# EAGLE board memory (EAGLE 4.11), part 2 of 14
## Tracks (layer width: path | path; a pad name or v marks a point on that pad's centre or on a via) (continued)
-(WTX*ROTR)  (via drill 0.61) (continued)
  Bottom 0.254: v173.35,353.7 174.62,354.97 179.07,354.97 A26.V2 | v293.37,412.12 292.74,412.75 268.61,412.75 267.97,413.39 251.46,413.39 250.19,414.66 196.85,414.66 195.58,413.39 v190.5,413.39
-(WTX*TAD)  (via drill 0.61)
  Top 0.254: v384.18,276.23 384.18,262.25 385.44,260.99 C10.E2 | v341,281.31 341,287.02 339.73,288.29 v339.73,339.73 | 319.4,353.06 319.4,354.97 A15.V2 | v319.4,341.63 319.4,353.06 | v311.79,385.45 314.32,382.91 314.32,358.14 319.4,353.06
  Route3 0.254: v286.38,391.16 284.48,393.06 284.48,396.24 A18.E2
  Bottom 0.254: v384.18,276.23 381.63,278.77 371.48,278.77 370.84,278.13 367.67,278.13 367.03,278.77 354.33,278.77 351.79,281.31 v341,281.31 | v339.73,339.73 337.82,341.63 v319.4,341.63 | v311.79,385.45 307.98,385.45 306.7,386.72 A16.J2 306.07,387.99 303.53,387.99 302.26,389.25 294.64,389.25 291.46,392.43 290.19,392.43 289.56,391.8 287.02,391.8 v286.38,391.16
-[(ISZ*ZI)+JMS+(OP+IOT)*SKP+JMP]  (via drill 0.61)
  Top 0.254: v224.79,327.03 225.43,327.66 225.43,339.09 224.16,340.36 224.16,344.81 227.97,348.62 227.97,351.79 226.06,353.7 226.06,354.33 v227.33,355.6
  Route2 0.254: v179.07,80.64 179.71,80.01 184.78,80.01 191.77,73.02 220.98,73.02 223.52,70.48 238.12,70.48 255.91,52.7 262.25,52.7 263.52,51.44 267.97,51.44 F19.F2 | v179.71,248.28 183.51,252.09 184.78,252.09 188.59,255.91 189.87,255.91 193.04,252.73 198.12,252.73 v199.39,254 | v227.33,355.6 229.87,353.06 v233.04,353.06 | v306.7,364.49 308.61,366.4 314.96,366.4 315.6,367.03 324.49,367.03 325.12,366.4 327.66,366.4 328.3,367.03 334.64,367.03 337.82,370.21 340.36,370.21 341,369.57 349.88,369.57 353.69,373.38 362.58,373.38 366.39,369.57 375.29,369.57 379.1,373.38 379.73,373.38 381,372.11 385.44,372.11 A10.P2
  Route3 0.254: v179.07,80.64 171.45,88.27 171.45,148.59 161.93,158.11 161.93,182.88 v160.66,184.15 | v169.54,187.96 171.45,189.86 171.45,215.26 174.62,218.44 174.62,241.94 179.71,247.01 v179.71,248.28 | v199.39,254 209.55,264.16 209.55,275.59 219.07,285.12 219.07,292.74 219.71,293.37 219.71,294 219.07,294.64 219.07,321.31 v224.79,327.03 | v300.99,358.78 v306.7,364.49
  Bottom 0.254: v160.66,184.15 162.56,186.06 167.64,186.06 v169.54,187.96 | v233.04,353.06 251.46,353.06 252.73,354.33 260.99,354.33 261.62,353.7 270.51,353.7 274.32,357.5 275.59,357.5 277.5,355.6 278.76,355.6 280.67,357.5 287.65,357.5 288.29,358.14 289.56,356.87 297.18,356.87 299.72,359.41 300.36,359.41 v300.99,358.78
-[A12*(EX+DC+LD)]  (via drill 0.61)
  Top 0.254: v74.3,230.5 79.38,235.59 79.38,275.59 80.64,276.86 v80.64,287.02 | v355.6,389.25 355.6,382.91 356.87,381.64 A12.L2
  Route2 0.254: v267.33,378.46 267.33,377.19 266.7,377.19 259.08,369.57 250.19,369.57 249.56,370.21 240.66,370.21 236.85,366.4 234.31,366.4 231.14,369.57 224.79,369.57 220.98,373.38 212.09,373.38 211.46,372.75 202.56,372.75 201.93,373.38 199.39,373.38 195.58,369.57 189.23,369.57 186.06,366.4 177.16,366.4 176.53,367.03 173.99,367.03 173.35,366.4 164.47,366.4 163.83,367.03 161.29,367.03 157.48,363.22 148.59,363.22 144.78,367.03 135.89,367.03 135.25,366.4 129.54,366.4 v125.09,361.95
  Route3 0.254: v80.64,287.02 79.38,288.29 79.38,296.55 78.11,297.81 B34.R2 | v313.06,390.53 301.62,379.1 301.62,373.38 298.45,370.21 295.91,370.21 286.38,379.73 275.59,379.73 275.59,377.83 274.32,376.56 267.97,376.56 267.97,377.83 v267.33,378.46 | v125.09,361.95 95.25,332.11 95.25,306.71 v93.34,304.8
  Bottom 0.254: v74.3,230.5 73.66,229.87 67.31,229.87 60.96,223.52 52.07,223.52 48.26,227.33 39.37,227.33 35.56,223.52 31.11,223.52 30.48,222.88 C38.U2 | v355.6,389.25 354.96,388.62 351.79,388.62 351.15,389.25 342.26,389.25 341.63,388.62 340.36,388.62 339.09,389.89 336.55,389.89 335.92,389.25 332.11,389.25 328.93,392.43 326.39,392.43 322.58,388.62 314.96,388.62 v313.06,390.53 | v93.34,304.8 92.08,303.53 85.09,303.53 80.64,299.09 78.11,299.09 B34.R2
-[WTD+WTE+WTF+EX+DC+(WTX*JMS)+WTB]
  Top 0.254: D09.L2 394.97,175.26 394.97,179.07 393.7,180.34 393.7,200.66 395.61,202.56 395.61,217.17 396.88,218.44 396.88,239.39 395.61,240.66 395.61,243.84 C09.L2
-[WTE*[(ISZ*ZI)+JMS+(OP+IOT)*SKP]]  (via drill 0.61)
  Top 0.254: v365.12,260.35 365.12,238.76 369.57,238.76 C11.N2 | v359.41,261.62 358.77,262.25 v358.77,346.08 | v330.2,346.08 v330.2,361.31 | v339.73,368.94 339.73,398.78 343.54,398.78 346.71,395.61 346.71,391.8 347.35,391.16 A13.H2
  Bottom 0.254: A18.S2 284.48,364.49 288.93,364.49 290.19,363.22 291.46,363.22 292.1,363.86 302.26,363.86 302.89,363.22 311.79,363.22 315.6,367.03 318.77,367.03 320.04,365.76 321.94,365.76 A15.S2 322.58,364.49 327.02,364.49 328.3,363.22 | v365.12,260.35 363.86,261.62 v359.41,261.62 | v358.77,346.08 358.14,346.71 330.83,346.71 v330.2,346.08 | v330.2,361.31 328.3,363.22 | v339.73,368.94 339.73,366.4 332.11,366.4 328.93,363.22 328.3,363.22
-[WTF*-(OP+IOT)]  (via drill 0.61)
  Top 0.254: v410.85,303.53 410.85,307.34 B08.M2
  Route2 0.254: v300.36,295.28 302.26,297.18 309.25,297.18 309.88,296.55 314.96,296.55 315.6,297.18 321.94,297.18 322.58,296.55 327.66,296.55 331.47,300.36 340.36,300.36 341,299.72 v341.63,299.72 | v360.68,299.72 361.31,300.36 365.76,300.36 366.39,299.72 375.29,299.72 379.1,303.53 387.99,303.53 391.8,299.72 400.69,299.72 404.5,303.53 v410.85,303.53
  Bottom 0.254: v300.36,295.28 297.18,295.28 B17.S2 | v341.63,299.72 342.26,300.36 353.06,300.36 353.69,299.72 v360.68,299.72
-[WTF+WTX*(JMP+JMS)+WTE+WTB+EX+DC+LD]  (via drill 0.61)
  Route2 0.254: v409.57,338.46 408.94,337.82 402.59,337.82 398.14,342.27 374.65,342.27 373.38,343.54 340.36,343.54 338.45,341.63 320.68,341.63 319.4,342.9 314.96,342.9 314.32,342.27 305.44,342.27 304.8,341.63 299.72,341.63 299.08,341 294,341 290.83,337.82 288.29,337.82 287.65,338.46 v287.02,338.46
  Route3 0.254: v409.57,338.46 409.57,320.04 412.12,317.5 412.12,316.23 410.85,316.23 410.21,316.87 408.31,316.87 B08.J2 | v287.02,338.46 285.75,337.19 285.75,328.93 284.48,327.66 B18.E2
-[WTX(TAD+IAC_CMA)]  (via drill 0.61)
  Top 0.254: v217.81,247.65 219.07,246.38 219.07,217.81 222.25,214.63 v222.25,144.14 | v309.25,143.51 309.88,142.88 v309.88,140.97
  Route2 0.254: v182.88,250.19 184.15,248.92 187.96,248.92 188.59,249.56 197.49,249.56 198.12,248.92 200.66,248.92 204.47,252.73 211.46,252.73 216.53,247.65 v217.81,247.65 | v309.88,140.97 319.4,140.97 322.58,137.79 327.66,137.79 328.3,138.43 330.83,138.43 334.01,135.25 338.45,135.25 347.98,125.73 349.88,125.73 350.52,125.09 353.06,125.09 353.69,125.73 354.96,125.73 357.5,123.19 366.39,132.08 374.01,132.08 v382.9,123.19
  Route3 0.254: v182.88,250.19 165.1,267.97 165.1,292.74 168.28,295.91 168.28,315.6 167,316.87 B27.J2 | v382.9,123.19 387.35,118.74 387.35,78.74 384.18,75.56 381.63,75.56 381.63,81.28 382.27,81.91 E10.V2
  Bottom 0.254: v222.25,144.14 261.62,144.14 263.52,142.24 303.53,142.24 304.8,143.51 v309.25,143.51
-[WTX*(JMP+JMS)]  (via drill 0.61)
  Top 0.254: v393.7,356.24 393.7,362.59 396.88,365.76 396.88,372.75 395.61,374.02 A09.N2 | v363.86,353.7 364.49,353.06 364.49,339.73 361.95,337.19 v361.95,330.84
  Bottom 0.254: B34.E2 81.28,327.66 81.92,328.3 86.36,328.3 87,328.93 95.89,328.93 96.52,328.3 99.06,328.3 99.69,328.93 107.31,328.93 107.95,328.3 111.76,328.3 112.39,328.93 121.28,328.93 121.92,328.3 124.46,328.3 125.09,328.93 133.99,328.93 134.62,328.3 137.16,328.3 137.79,328.93 146.69,328.93 147.32,328.3 149.86,328.3 150.5,328.93 159.38,328.93 160.02,328.3 162.56,328.3 163.19,328.93 172.09,328.93 172.72,328.3 175.26,328.3 175.9,328.93 184.78,328.93 185.42,328.3 187.96,328.3 188.59,328.93 197.49,328.93 198.12,328.3 200.66,328.3 201.29,328.93 210.19,328.93 210.82,328.3 213.36,328.3 214,328.93 222.88,328.93 223.52,328.3 226.06,328.3 226.69,328.93 235.59,328.93 236.22,328.3 238.76,328.3 239.4,328.93 248.28,328.93 248.92,328.3 251.46,328.3 252.09,328.93 260.99,328.93 261.62,328.3 264.16,328.3 264.8,328.93 273.69,328.93 274.32,328.3 276.86,328.3 277.5,328.93 278.76,328.93 279.4,328.3 289.56,328.3 290.19,328.93 299.08,328.93 299.72,328.3 302.26,328.3 302.89,328.93 311.79,328.93 312.42,328.3 314.96,328.3 315.6,328.93 316.87,328.93 317.5,328.3 327.66,328.3 328.3,328.93 337.19,328.93 337.82,328.3 340.36,328.3 341,328.93 346.07,328.93 347.35,327.66 B13.E2 347.98,327.66 350.52,327.66 354.33,331.47 358.14,331.47 358.77,330.84 v361.95,330.84 | v393.7,356.24 393.7,353.7 v363.86,353.7
-A  (via drill 0.61)
  Top 0.254: A32.N2 103.5,375.29 104.78,376.56 104.78,379.1 106.05,380.37 106.05,383.54 A32.K2 | 117.47,376.56 116.2,375.29 A31.N2 | 117.47,376.56 117.47,382.27 118.75,383.54 A31.K2 | A29.K2 144.78,384.81 146.05,386.08 146.05,393.06 141.6,397.51 141.6,399.42 A29.D2 | 130.18,382.27 130.18,376.56 128.91,375.29 A30.N2 | 130.18,382.27 131.44,383.54 A30.K2 | 130.18,382.27 130.18,398.15 128.91,399.42 A30.D2 | 117.47,376.56 117.47,360.68 118.75,359.41 A31.U2 | 117.47,325.75 117.47,328.3 116.2,329.56 B31.D2 | 117.47,325.75 117.47,294 116.2,292.74 B31.T2 | 130.18,328.3 130.18,325.12 | 130.18,325.12 130.18,316.87 | 130.18,316.87 130.18,300.36 128.91,299.09 B30.R2 | 130.18,328.3 128.91,329.56 B30.D2 | 139.7,329.56 136.53,329.56 136.53,323.22 134.62,321.31 | 139.7,329.56 140.97,329.56 B29.D2 | 130.18,316.87 134.62,321.31 | 134.62,321.31 v141.6,314.33 | v266.7,341.63 266.7,332.11 267.97,330.84 B19.D2 | v140.34,341.63 139.7,341 139.7,329.56 | 117.47,325.75 124.46,325.75 125.09,325.12 130.18,325.12 | 130.18,328.3 130.18,356.87 131.44,358.14 A30.U2
  Route2 0.254: v141.6,314.33 144.15,314.33 B29.K2
  Bottom 0.254: A32.U2 106.68,359.41 107.31,360.05 111.76,360.05 112.39,360.68 117.47,360.68 118.75,359.41 A31.U2 119.38,359.41 121.92,359.41 123.19,360.68 130.18,360.68 131.44,359.41 A30.U2 | A32.K2 106.68,384.81 111.12,384.81 112.39,386.08 113.67,386.08 114.94,384.81 118.75,384.81 A31.K2 | A32.D2 103.5,400.69 104.78,401.96 111.76,401.96 113.03,400.69 115.57,400.69 A31.D2 116.2,400.69 117.47,401.96 124.46,401.96 125.73,400.69 128.27,400.69 A30.D2 | A29.K2 144.15,384.81 139.7,384.81 138.43,386.08 137.79,386.08 136.53,384.81 132.08,384.81 A30.K2 | A31.N2 116.2,374.02 117.47,372.75 124.46,372.75 125.73,374.02 128.27,374.02 A30.N2 | v140.34,341.63 v266.7,341.63
-A00  (via drill 0.61)
  Top 0.254: v114.3,205.74 114.3,163.83 115.57,162.56 D31.R2 | v357.5,111.76 355.6,113.66 v355.6,139.7 | v121.28,141.6 120.65,142.24 v120.65,161.29 | 44.45,278.13 44.45,249.56 43.18,248.28 C37.K2 | 44.45,278.13 44.45,328.3 | 44.45,328.3 44.45,369.57 43.18,370.84 A37.P2 | 44.45,328.3 v45.09,328.3 | v146.05,279.4 146.05,306.07 144.78,307.34 B29.M2 144.78,308.61 144.78,312.42 149.22,316.87 149.22,345.44 v153.03,349.25 | 44.45,278.13 v46.35,278.13 | v252.73,400.05 250.82,398.15 v250.82,348.62
  Route2 0.254: v357.5,111.76 360.05,111.76 E12.K2 | v252.73,400.05 255.27,400.05 A20.D2
  Route3 0.254: 31.75,206.38 v31.75,247.01 31.75,252.09 30.48,253.36 C38.H2 | 31.75,206.38 31.75,179.7 30.48,178.44 D38.K2 | v30.48,206.38 31.75,206.38
  Bottom 0.254: v114.3,205.74 46.35,205.74 45.72,206.38 v30.48,206.38 | v355.6,139.7 354.96,140.34 321.31,140.34 320.68,139.7 313.69,139.7 312.42,138.43 306.07,138.43 305.44,139.06 297.81,139.06 297.18,138.43 293.37,138.43 292.1,139.7 142.88,139.7 140.97,141.6 v121.28,141.6 | v120.65,161.29 116.2,161.29 D31.R2 | v31.75,247.01 33.02,247.01 34.29,245.75 36.83,245.75 38.1,247.01 42.55,247.01 C37.K2 | v45.09,328.3 46.35,328.3 46.99,328.93 49.53,328.93 50.16,328.3 59.05,328.3 59.69,328.93 62.23,328.93 62.87,328.3 71.75,328.3 72.39,328.93 76.83,328.93 77.47,329.56 B34.D2 | v146.05,279.4 145.41,280.04 59.69,280.04 59.05,279.4 48.9,279.4 47.62,278.13 v46.35,278.13 | v250.82,348.62 235.59,348.62 234.31,349.89 225.43,349.89 224.79,349.25 210.82,349.25 210.19,349.89 181.61,349.89 180.97,350.52 167.64,350.52 167,349.89 153.67,349.89 v153.03,349.25
-A1  (via drill 0.61)
  Top 0.254: v408.31,271.78 407.04,273.05 407.04,281.31 v407.67,281.94
  Route2 0.254: v408.31,97.79 422.91,112.39 427.36,112.39 434.98,120.02 434.98,142.88 436.25,144.14 436.25,151.13 435.61,151.13 434.98,151.76 434.98,163.83 v433.7,163.83 | v442.6,217.81 442.6,219.07 447.68,224.16 447.68,233.04 442.6,233.04 409.57,266.06 409.57,271.78 v408.31,271.78 | v407.67,281.94 396.24,293.37 389.89,293.37 388.62,294.64 386.08,294.64 B10.S2
  Route3 0.254: v442.6,180.97 441.96,181.61 441.96,182.88 441.32,183.51 441.32,184.78 442.6,186.06 442.6,188.59 441.32,189.86 441.32,206.38 442.6,207.64 v442.6,217.81
  Bottom 0.254: v408.31,97.79 401.32,90.8 396.88,90.8 395.61,89.53 E09.T2 | v433.7,163.83 433.7,167 432.44,167 431.8,167.64 431.8,175.89 436.88,175.89 441.96,180.97 v442.6,180.97
-A12  (via drill 0.61)
  Top 0.254: C38.S2 29.84,229.23 29.84,234.31 C38.P2 29.84,235.59 28.57,236.85 v28.57,283.85 | B35.D2 64.77,329.56 63.5,328.3 63.5,308.61 64.77,307.34 64.77,305.44 B35.N2 64.77,304.17 63.5,302.9 63.5,285.75 v61.59,283.85 | B27.S2 169.54,295.91 169.54,300.99 B27.P2 170.18,302.26 170.18,306.07 171.45,307.34 171.45,318.77 170.18,320.04 B27.H2 | v266.7,393.7 266.7,398.15 267.97,399.42 A19.D2 267.97,400.69 266.7,401.96 v266.7,420.37 | v309.88,394.97 309.88,391.16 A16.H2 | B30.T2 128.91,291.47 128.91,289.56 138.43,280.04 138.43,276.23 139.7,274.96 140.97,274.96 140.97,285.12 B29.V2 141.6,286.39 142.88,287.66 142.88,306.71 | A28.S2 157.48,365.76 158.75,367.03 158.75,388.62 157.48,389.89 A28.H2 156.84,391.16 156.84,396.24 A28.E2 157.48,397.51 158.75,398.78 v158.75,419.1 | A29.N2 141.6,374.02 141.6,371.48 v147.96,365.12 142.88,360.05 142.88,306.71 | 142.88,306.71 v143.51,306.71 | v122.56,295.28 120.65,297.18 120.65,312.42 119.38,313.69 B31.K2 | F37.P2 42.55,27.94 42.55,22.86 F37.S2 43.18,21.59 47.62,21.59 v47.62,4.44 | v473.07,5.71 473.07,13.97 474.35,15.24 F03.U2 | v395.61,1.9 393.7,3.81 393.7,156.84 394.97,158.11 394.97,161.29 D09.R2 395.61,162.56 395.61,163.19 396.88,164.47 396.88,191.77 395.61,193.04 D09.D2 | F23.K2 220.98,40.64 221.62,40.01 221.62,36.2 222.25,35.56 222.25,4.44 v222.88,3.81 222.88,2.54 v222.25,1.9 | v33.66,179.07 33.66,176.53 34.92,175.26 v34.92,162.56
  Route3 0.254: v33.66,227.33 34.92,226.06 34.92,180.34 v33.66,179.07 | v34.92,162.56 34.92,51.44 44.45,41.91 44.45,30.48 43.18,29.21 F37.P2
  Bottom 0.254: B35.N2 65.41,304.17 66.67,302.9 73.66,302.9 74.93,304.17 77.47,304.17 B34.N2 78.11,304.8 80.64,304.8 85.72,309.88 87.63,309.88 88.27,309.25 97.16,309.25 100.97,313.06 109.86,313.06 110.49,312.42 113.03,312.42 114.3,313.69 118.75,313.69 B31.K2 | v28.57,283.85 29.21,283.21 52.07,283.21 52.7,283.85 v61.59,283.85 | B22.J2 229.87,317.5 226.06,317.5 224.16,319.41 215.26,319.41 214.63,318.77 212.09,318.77 211.46,319.41 202.56,319.41 201.93,318.77 199.39,318.77 198.75,319.41 191.77,319.41 191.13,318.77 186.69,318.77 186.06,319.41 177.16,319.41 176.53,318.77 175.26,318.77 173.99,320.04 170.18,320.04 B27.H2 | v266.7,393.7 266.7,395.61 274.32,395.61 277.5,398.78 286.38,398.78 287.02,398.15 289.56,398.15 290.19,398.78 297.18,398.78 300.99,394.97 v309.88,394.97 | v147.96,365.12 149.86,363.22 155.57,363.22 156.84,364.49 A28.S2 | v266.7,420.37 266.06,421 173.99,421 172.09,419.1 v158.75,419.1 | v143.51,306.71 147.96,306.71 148.59,306.07 151.13,306.07 151.76,306.71 160.66,306.71 163.83,303.53 168.28,303.53 169.54,302.26 B27.P2 | v122.56,295.28 125.09,292.74 128.27,292.74 B30.T2 | D10.D2 382.9,194.31 384.18,195.58 389.89,195.58 391.8,193.67 394.97,193.67 D09.D2 | v473.07,5.71 469.26,1.9 v395.61,1.9 394.97,2.54 377.82,2.54 376.56,1.27 288.93,1.27 287.02,3.17 285.12,3.17 283.85,1.9 224.79,1.9 v222.88,3.81 | v47.62,4.44 51.44,0.63 198.12,0.63 200.03,2.54 200.66,1.9 v222.25,1.9 | v33.66,227.33 31.11,227.33 30.48,227.97 C38.S2
-A13  (via drill 0.61)
  Top 0.254: v222.25,58.42 v222.25,70.48 222.25,102.87 223.52,104.14 v223.52,104.77 | v349.25,71.75 v349.25,80.64 349.25,109.22 352.43,112.39 v352.43,127 | D31.J2 116.2,181.61 116.84,182.25 116.84,186.06 117.47,186.69 117.47,218.44 123.83,224.79 123.83,316.87 128.27,321.31 128.27,323.22 B30.F2 | v155.57,323.85 155.57,328.3 154.31,329.56 B28.D2 | B10.N2 382.9,305.44 382.9,309.25 385.44,311.79 385.44,313.69 B10.K2 | B12.U2 360.68,289.56 361.95,290.83 361.95,312.42 360.68,313.69 B12.K2 360.68,314.96 361.95,316.23 v361.95,329.56 | v274.32,363.86 276.23,363.86 276.23,332.74 v279.4,329.56
  Route2 0.254: B12.D2 356.87,329.56 353.06,329.56 351.79,328.3 350.52,328.3 349.88,328.93 341,328.93 340.36,328.3 337.82,328.3 337.19,328.93 328.3,328.93 327.66,328.3 317.5,328.3 316.87,328.93 315.6,328.93 314.96,328.3 312.42,328.3 311.79,328.93 302.89,328.93 302.26,328.3 299.72,328.3 299.08,328.93 290.19,328.93 289.56,328.3 280.67,328.3 v279.4,329.56 278.13,329.56 276.86,328.3 274.32,328.3 273.69,328.93 264.8,328.93 264.16,328.3 257.81,328.3 254.63,325.12 252.09,325.12 248.28,328.93 239.4,328.93 238.76,328.3 236.22,328.3 235.59,328.93 226.69,328.93 226.06,328.3 223.52,328.3 222.88,328.93 214,328.93 213.36,328.3 210.82,328.3 210.19,328.93 201.29,328.93 200.66,328.3 198.12,328.3 197.49,328.93 188.59,328.93 187.96,328.3 185.42,328.3 184.78,328.93 175.9,328.93 175.26,328.3 172.72,328.3 172.09,328.93 163.19,328.93 160.02,325.75 157.48,325.75 v155.57,323.85 | v223.52,104.77 219.07,109.22 214,109.22 207.65,115.57 205.74,115.57 174.62,146.69 171.45,146.69 167.64,150.5 v163.19,150.5
  Route3 0.254: v297.18,70.48 v297.18,73.02 | v268.61,365.12 268.61,367.67 A19.R2 | v128.91,157.48 120.65,165.73 120.65,173.99 116.2,178.44 116.2,180.34 D31.J2
  Bottom 0.254: v222.25,58.42 218.44,58.42 217.81,57.79 F23.D2 | v222.25,70.48 236.22,70.48 236.85,71.12 296.55,71.12 v297.18,70.48 | v297.18,73.02 297.81,72.39 300.99,72.39 301.62,71.75 303.53,71.75 304.17,71.12 348.62,71.12 v349.25,71.75 | v352.43,127 356.87,127 E12.D2 | v349.25,80.64 401.95,80.64 402.59,81.28 408.31,81.28 408.94,80.64 446.4,80.64 455.93,90.17 462.28,90.17 467.36,95.25 471.17,95.25 E03.R2 | v155.57,323.85 155.57,323.22 154.94,322.58 148.59,322.58 147.96,321.95 139.06,321.95 138.43,322.58 135.89,322.58 135.25,321.95 130.18,321.95 128.91,323.22 B30.F2 | B12.U2 360.68,289.56 361.31,290.2 365.76,290.2 366.39,290.83 368.3,290.83 370.2,288.93 372.75,288.93 B11.U2 373.38,288.29 375.92,288.29 377.19,287.02 384.18,287.02 385.44,288.29 B10.U2 386.08,289.56 388.62,289.56 389.89,290.83 396.88,290.83 398.14,289.56 B09.U2 | B12.K2 360.68,314.96 365.12,314.96 366.39,316.23 367.67,316.23 368.94,314.96 372.75,314.96 B11.K2 373.38,314.96 377.82,314.96 379.1,316.23 380.37,316.23 381.63,314.96 385.44,314.96 B10.K2 | B12.N2 357.5,304.17 358.77,302.9 365.76,302.9 367.03,304.17 369.57,304.17 B11.N2 370.2,304.17 371.48,302.9 378.46,302.9 379.73,304.17 382.27,304.17 B10.N2 382.9,304.17 384.18,302.9 389.25,302.9 391.16,304.8 394.97,304.8 B09.N2 | 361.95,328.3 365.76,328.3 367.03,329.56 369.57,329.56 B11.D2 370.2,329.56 371.48,328.3 376.56,328.3 377.19,328.93 381.63,328.93 382.27,329.56 B10.D2 | 361.95,328.3 358.77,328.3 357.5,329.56 B12.D2 | v268.61,365.12 269.88,363.86 v274.32,363.86 | 361.95,328.3 v361.95,329.56 | v163.19,150.5 162.56,151.13 154.31,151.13 153.67,150.5 152.4,151.76 152.4,154.31 148.59,154.31 147.96,153.67 139.06,153.67 135.25,157.48 v128.91,157.48
-A13(B)  (via drill 0.61)
  Top 0.254: v99.69,87.63 98.42,88.9 98.42,137.79 100.97,140.34 100.97,151.13 101.6,151.76 101.6,170.81 104.78,173.99 104.78,178.44 v106.68,180.34
  Route2 0.254: v106.68,180.34 113.03,186.69 115.57,186.69 D31.F2
  Bottom 0.254: v99.69,87.63 102.87,87.63 102.87,83.18 E32.V2
-A(00-01)  (via drill 0.61)
  Route2 0.254: v291.46,393.7 286.38,398.78 276.86,398.78 273.05,394.97 262.89,394.97 262.25,395.61 253.37,395.61 249.56,391.8 240.66,391.8 236.85,395.61 227.97,395.61 224.16,391.8 219.71,391.8 v215.26,387.35
  Route3 0.254: v141.6,326.39 141.6,324.49 B29.F2 | v215.26,387.35 196.85,368.94 196.85,363.86 193.68,360.68 193.68,341.63 184.15,332.11 184.15,328.93 185.42,327.66 v182.25,324.49
  Bottom 0.254: v141.6,326.39 142.24,325.75 146.05,325.75 146.69,326.39 149.22,326.39 150.5,325.12 159.38,325.12 160.02,325.75 162.56,325.75 163.19,325.12 168.28,325.12 169.54,326.39 B27.E2 170.18,326.39 173.99,326.39 175.26,325.12 176.53,325.12 177.16,324.49 177.8,324.49 177.8,323.22 178.44,322.58 180.34,322.58 v182.25,324.49 | v291.46,393.7 293.37,391.8 300.36,391.8 300.99,392.43 311.15,392.43 311.15,394.97 309.88,396.24 A16.E2
-A(00-11)  (via drill 0.61)
  Top 0.254: v133.35,302.26 133.35,312.42 132.08,313.69 B30.K2 | A16.P2 309.25,370.84 309.25,365.76 A16.S2 309.25,364.49 307.98,363.22 v307.98,350.52 | B18.K2 283.85,314.96 283.21,315.6 283.21,318.77 282.57,319.41 282.57,328.3 281.31,329.56 B18.D2 280.67,330.84 279.4,332.11 v279.4,353.7
  Route2 0.254: v366.39,231.78 358.77,239.39 353.69,239.39 349.25,243.84 v347.98,243.84 | v328.3,299.09 321.31,306.07 313.69,306.07 309.88,309.88 300.99,309.88 297.18,306.07 288.29,306.07 287.65,306.71 287.02,306.71 285.75,307.98 285.75,313.69 284.48,313.69 B18.K2
  Route3 0.254: v114.3,318.14 114.3,321.95 115.57,323.22 B31.F2 | v382.9,222.25 385.44,219.71 385.44,208.28 384.18,207.01 384.18,179.7 385.44,178.44 D10.K2 | v341,244.47 339.73,245.75 339.73,281.94 330.2,291.47 330.2,297.18 v328.3,299.09
  Bottom 0.254: v133.35,302.26 136.53,299.09 140.97,299.09 B29.R2 | v114.3,318.14 114.3,315.6 124.46,315.6 125.09,316.23 130.18,316.23 131.44,314.96 B30.K2 132.08,314.96 132.72,315.6 137.16,315.6 137.79,316.23 146.69,316.23 147.32,315.6 149.86,315.6 150.5,316.23 159.38,316.23 160.02,315.6 162.56,315.6 163.19,316.23 172.09,316.23 172.72,315.6 175.26,315.6 175.9,316.23 184.78,316.23 185.42,315.6 187.96,315.6 188.59,316.23 197.49,316.23 198.12,315.6 200.66,315.6 201.29,316.23 210.19,316.23 210.82,315.6 213.36,315.6 214,316.23 222.88,316.23 223.52,315.6 226.06,315.6 226.69,316.23 228.6,316.23 230.5,314.33 233.04,314.33 B22.K2 233.68,314.96 234.31,315.6 238.76,315.6 239.4,316.23 248.28,316.23 248.92,315.6 251.46,315.6 252.09,316.23 260.99,316.23 261.62,315.6 264.16,315.6 264.8,316.23 273.69,316.23 274.32,315.6 276.86,315.6 277.5,316.23 282.57,316.23 283.85,314.96 B18.K2 | D10.K2 386.08,178.44 390.52,178.44 391.8,179.7 392.43,179.7 393.7,178.44 398.14,178.44 D09.K2 | v307.98,350.52 307.34,349.89 294.64,349.89 291.46,353.06 280.04,353.06 v279.4,353.7 | v382.9,222.25 377.82,227.33 370.84,227.33 v366.39,231.78 | v347.98,243.84 347.35,243.2 342.9,243.2 341.63,244.47 v341,244.47
-A(00-12)
  Top 0.254: B28.N2 154.31,304.17 154.94,303.53 154.94,299.72 155.57,299.09 155.57,291.47 156.84,290.2 156.84,289.56 B28.U2
  Bottom 0.254: B29.T2 141.6,291.47 142.88,290.2 149.86,290.2 150.5,290.83 153.67,290.83 155.57,288.93 156.84,288.93 B28.U2
-AC11  (via drill 0.61)
  Top 0.254: v468,363.22 469.9,363.22 469.9,375.92 476.25,382.27 476.25,394.97 474.98,396.24 A03.E2 | v190.5,355.6 190.5,366.4 191.77,367.67 A25.R2 | v393.06,350.52 396.88,350.52 398.14,351.79 397.51,352.43 397.51,357.5 396.88,358.14 396.88,363.22 398.14,364.49 A09.S2 | v459.11,358.14 459.11,361.31 A04.T2
  Route2 0.254: v468,363.22 467.36,363.86 460.38,363.86 459.11,362.59 A04.T2
  Bottom 0.254: v190.5,355.6 190.5,353.06 210.82,353.06 212.09,351.79 247.65,351.79 248.92,350.52 249.56,351.16 270.51,351.16 271.78,349.89 288.29,349.89 290.19,351.79 293.37,348.62 324.49,348.62 325.12,349.25 357.5,349.25 358.77,350.52 v393.06,350.52 396.88,350.52 398.14,351.79 397.51,352.43 398.78,353.7 440.06,353.7 443.87,357.5 452.75,357.5 453.39,356.87 457.83,356.87 v459.11,358.14
-AM  (via drill 0.61)
  Top 0.254: v215.26,115.57 215.9,114.93 215.9,84.45 217.17,83.18 E23.V2 | v63.5,97.79 63.5,165.73 v62.23,167
  Bottom 0.254: v215.26,115.57 216.53,116.84 220.34,116.84 E23.H2 | 61.59,96.52 60.96,97.16 56.52,97.16 55.88,97.79 E36.P2 | 61.59,96.52 62.23,96.52 v63.5,97.79 | v62.23,167 55.24,173.99 52.7,173.99 D36.L2 | 61.59,96.52 74.3,83.82 74.93,83.82 75.56,84.45 85.72,84.45 85.72,82.55 87.63,80.64 88.9,80.64 88.9,83.18 89.53,83.82 93.98,83.82 100.33,90.17 106.68,90.17 110.49,93.98 120.65,93.98 124.46,90.17 132.08,90.17 135.89,93.98 144.78,93.98 148.59,90.17 157.48,90.17 161.29,93.98 163.83,93.98 164.47,93.34 173.35,93.34 173.99,93.98 182.88,93.98 189.87,86.99 198.75,86.99 199.39,87.63 207.65,87.63 210.82,90.8 212.72,90.8 215.9,87.63 222.25,87.63 222.25,85.09 221.62,84.45 219.07,84.45 217.81,83.18 E23.V2
-AND  (via drill 0.61)
  Top 0.254: 260.35,182.88 260.35,218.44 259.08,219.71 260.35,220.98 v260.35,294 260.35,309.25 259.08,310.52 259.08,313.69 B20.K2 | 260.35,182.88 260.35,151.76 259.08,150.5 259.08,149.86 260.35,148.59 260.35,85.09 259.08,83.82 259.08,69.85 v259.71,69.22 260.35,68.58 260.35,55.88 259.08,54.61 F20.E2 | v314.32,65.41 v314.32,26.03 | 260.35,182.88 v262.25,182.88
  Route2 0.254: v293.37,67.94 v293.37,65.41 | v266.06,180.97 267.97,182.88 276.23,182.88 292.1,167 296.55,167 296.55,170.81 D17.M2
  Route3 0.254: v347.35,311.15 347.35,313.69 B13.K2 | v332.11,309.25 333.38,307.98 v333.38,304.8
  Bottom 0.254: v314.32,26.03 318.77,26.03 F15.R2 | v314.32,65.41 304.17,65.41 303.53,64.77 300.99,64.77 300.36,65.41 v293.37,65.41 | v293.37,67.94 291.46,69.85 260.35,69.85 v259.71,69.22 | v266.06,180.97 265.43,181.61 263.52,181.61 v262.25,182.88 | v347.35,311.15 346.07,309.88 339.09,309.88 338.45,309.25 v332.11,309.25 | v333.38,304.8 333.38,303.53 327.02,303.53 320.68,297.18 313.69,297.18 313.06,296.55 304.17,296.55 303.53,297.18 300.99,297.18 300.36,296.55 291.46,296.55 290.83,297.18 288.29,297.18 287.65,296.55 278.76,296.55 278.13,297.18 275.59,297.18 271.78,293.37 262.89,293.37 262.25,294 v260.35,294
-AST  (via drill 0.61)
  Route2 0.254: v357.5,176.53 358.77,176.53 378.46,156.84 381.63,156.84 382.27,156.21 D10.T2 | v338.45,236.22 337.82,236.22 334.64,239.39 326.39,239.39 322.58,243.2 313.69,243.2 313.06,242.57 304.17,242.57 297.18,249.56 295.91,249.56 295.27,250.19 294.64,249.56 288.29,249.56 v287.65,248.92
  Route3 0.254: v357.5,176.53 353.06,180.97 353.06,182.88 352.43,183.51 352.43,189.23 351.15,190.5 351.15,191.77 352.43,193.04 352.43,206.38 353.69,207.64 353.69,220.34 352.43,221.61 352.43,231.14 353.69,232.41 v353.69,233.04 | v274.95,252.73 273.69,254 273.69,255.91 273.05,256.54 273.05,274.96 269.88,278.13 269.88,307.34 263.52,313.69 263.52,339.09 256.54,346.08 256.54,354.33 255.91,354.97 A20.V2
  Bottom 0.254: v353.69,233.04 353.06,233.68 344.81,233.68 341.63,236.85 339.09,236.85 v338.45,236.22 | v287.65,248.92 280.04,248.92 277.5,251.46 276.23,251.46 v274.95,252.73
-BAC00  (via drill 0.61)
  Top 0.254: v194.94,11.43 197.49,11.43 208.28,0.63 284.48,0.63 v284.48,5.71
  Route2 0.254: v17.78,100.33 21.59,96.52 23.5,96.52 109.22,10.79 163.83,10.79 164.47,11.43 172.09,11.43 172.72,10.79 194.31,10.79 v194.94,11.43 | v284.48,5.71 288.93,1.27 374.65,1.27 379.1,5.71 405.13,5.71 v406.4,6.98 | v424.18,100.96 438.15,114.93 438.15,137.79 436.88,139.06 436.88,151.13 437.51,151.13 441.32,154.94 441.32,182.25 443.23,182.25 445.77,184.78 445.77,186.69 D05.F2
  Route3 0.254: v406.4,6.98 412.75,13.34 412.75,59.05 419.1,65.41 419.1,85.09 425.45,91.44 425.45,99.69 v424.18,100.96
  Bottom 0.254: v17.78,100.33 13.34,100.33 10.16,103.5 3.17,103.5 3.17,118.11 10.79,125.73 13.34,125.73 13.97,126.36 E39.D2
-BAC01  (via drill 0.61)
  Route2 0.254: v80.64,149.86 73.03,142.24 71.75,142.24 60.96,131.44 54.61,131.44 45.09,121.92 36.2,121.92 32.38,125.73 23.5,125.73 22.86,125.09 18.41,125.09 17.78,124.46 E39.E2 | v125.73,154.31 126.36,153.67 137.16,153.67 140.97,157.48 149.86,157.48 150.5,156.84 159.38,156.84 160.02,157.48 162.56,157.48 163.19,156.84 169.54,156.84 175.9,150.5 v176.53,150.5 | v182.88,149.86 193.04,139.7 234.31,139.7 242.57,131.44 251.46,131.44 259.71,139.7 294,139.7 295.27,138.43 305.44,138.43 312.42,131.44 314.96,131.44 315.6,132.08 322.58,132.08 332.11,122.55 340.36,122.55 344.17,118.74 350.52,118.74 353.69,115.57 362.58,115.57 366.39,119.38 367.67,119.38 370.84,116.2 375.92,116.2 379.1,119.38 384.81,119.38 v389.25,123.82 | v398.78,174.62 409.57,185.42 416.56,185.42 422.91,191.77 429.26,191.77 429.89,192.41 435.61,192.41 v436.25,193.04
  Route3 0.254: v389.25,123.82 389.89,124.46 389.89,125.73 390.52,126.36 390.52,135.89 389.25,137.16 389.25,147.32 390.52,148.59 390.52,154.94 393.7,158.11 393.7,164.47 400.05,170.81 400.05,172.72 398.78,173.99 v398.78,174.62 | v436.25,193.04 438.15,191.13 438.15,189.23 436.88,187.96 v436.88,187.32
  Bottom 0.254: v80.64,149.86 83.19,147.32 99.06,147.32 102.87,151.13 111.76,151.13 112.39,150.5 121.28,150.5 125.09,154.31 v125.73,154.31 | v176.53,150.5 182.25,150.5 v182.88,149.86 | v436.88,187.32 441.96,182.25 445.13,182.25 445.77,181.61 D05.J2
-BAC02  (via drill 0.61)
  Route2 0.254: v49.53,115.57 52.7,118.74 59.69,118.74 80.01,139.06 97.16,139.06 105.41,147.32 143.51,147.32 147.32,151.13 149.86,151.13 v150.5,150.5 | v182.25,156.21 180.97,157.48 180.97,179.7 178.44,179.7 171.45,186.69 171.45,191.77 172.72,191.77 175.9,188.59 184.78,188.59 185.42,189.23 187.96,189.23 191.77,185.42 200.66,185.42 204.47,189.23 213.36,189.23 214,188.59 222.88,188.59 223.52,189.23 225.43,189.23 v229.87,184.78 | v252.73,180.97 257.18,185.42 264.16,185.42 270.51,191.77 275.59,191.77 v277.5,193.67 | v376.56,177.8 381.63,172.72 391.16,172.72 391.8,173.35 394.33,173.35 401.32,166.37 403.23,166.37 v405.13,168.28 | v427.36,170.18 427.99,169.54 430.53,169.54 434.98,173.99 v436.25,173.99
  Route3 0.254: v372.75,188.59 374.65,186.69 374.65,179.7 v376.56,177.8
  Bottom 0.254: v49.53,115.57 48.9,115.57 48.26,116.2 40.64,116.2 37.47,119.38 36.2,119.38 32.38,115.57 23.5,115.57 22.86,116.2 18.41,116.2 17.78,116.84 E39.H2 | v150.5,150.5 153.03,147.95 159.38,147.95 160.02,147.32 161.29,147.32 165.1,151.13 172.72,151.13 178.44,156.84 181.61,156.84 v182.25,156.21 | v229.87,184.78 230.5,185.42 234.95,185.42 235.59,184.78 238.12,184.78 239.4,186.06 246.38,186.06 251.46,180.97 v252.73,180.97 | v277.5,193.67 278.76,193.67 280.67,195.58 288.29,195.58 290.83,193.04 292.1,193.04 293.37,191.77 302.26,191.77 302.89,192.41 311.79,192.41 315.6,188.59 316.87,188.59 320.04,191.77 327.66,191.77 328.3,192.41 337.19,192.41 337.82,191.77 340.36,191.77 341,192.41 343.54,192.41 346.71,189.23 353.06,189.23 353.69,188.59 362.58,188.59 363.22,189.23 365.76,189.23 366.39,188.59 v372.75,188.59 | v405.13,168.28 407.04,170.18 413.38,170.18 414.65,171.45 415.29,171.45 417.19,169.54 426.08,169.54 426.72,170.18 v427.36,170.18 | v436.25,173.99 438.79,176.53 441.96,176.53 443.23,175.26 445.77,175.26 D05.L2
-BAC03  (via drill 0.61)
  Top 0.254: v185.42,157.48 189.23,161.29 v189.23,161.92 | v266.7,210.19 v266.7,183.51 | v352.43,207.64 357.5,202.56 v357.5,201.93
  Route2 0.254: v153.67,151.76 146.69,144.78 105.41,144.78 85.72,125.09 78.74,125.09 69.22,115.57 60.33,115.57 59.69,116.2 51.44,116.2 47.62,112.39 39.37,112.39 35.56,116.2 26.67,116.2 22.86,112.39 18.41,112.39 17.78,111.76 E39.K2 | v236.85,160.02 252.73,175.89 259.08,175.89 v266.7,183.51 | v357.5,201.93 365.76,201.93 366.39,201.29 375.29,201.29 375.92,201.93 378.46,201.93 379.1,201.29 381.63,201.29 385.44,205.1 412.12,205.1 412.75,204.47 414.65,204.47 417.83,207.64 428.62,207.64 430.53,205.74 437.51,205.74 438.15,205.1 440.69,205.1 443.23,207.64 v448.31,207.64 | v450.85,186.69 450.85,176.53 446.4,172.09 446.4,168.91 D05.N2
  Route3 0.254: v448.31,207.64 450.85,205.1 v450.85,186.69
  Bottom 0.254: v153.67,151.76 155.57,153.67 162.56,153.67 163.19,154.31 169.54,154.31 170.18,153.67 173.99,153.67 177.8,157.48 v185.42,157.48 | v189.23,161.92 191.13,163.83 200.66,163.83 201.29,163.19 210.19,163.19 210.82,163.83 213.36,163.83 214,163.19 222.88,163.19 223.52,163.83 226.06,163.83 226.69,163.19 233.04,163.19 236.22,160.02 v236.85,160.02 | v266.7,210.19 267.33,210.82 314.32,210.82 314.96,210.19 331.47,210.19 332.11,209.55 344.17,209.55 346.71,207.01 351.79,207.01 v352.43,207.64
-BAC04  (via drill 0.61)
  Top 0.254: v315.6,198.75 321.94,205.1 v321.94,218.44
  Route2 0.254: v43.18,113.66 54.61,125.09 59.69,125.09 81.92,147.32 90.81,147.32 116.2,172.72 123.19,172.72 129.54,179.07 135.89,179.07 v137.79,180.97 | v151.13,187.32 153.03,189.23 158.75,189.23 165.1,195.58 175.26,195.58 179.07,191.77 187.96,191.77 188.59,192.41 197.49,192.41 201.29,188.59 202.56,188.59 205.74,191.77 213.36,191.77 214,192.41 222.88,192.41 223.52,191.77 226.06,191.77 226.69,192.41 235.59,192.41 239.4,188.59 247.65,188.59 257.18,198.12 262.89,198.12 263.52,198.75 273.69,198.75 277.5,194.94 285.75,194.94 292.74,201.93 302.26,201.93 302.89,201.29 309.25,201.29 312.42,198.12 314.96,198.12 v315.6,198.75 | v321.94,218.44 323.21,217.17 327.02,217.17 333.38,223.52 339.73,223.52 349.88,233.68 349.88,236.22 353.06,236.22 353.69,236.85 354.96,236.85 v360.05,231.78 | v367.03,244.47 368.3,245.75 372.75,245.75 381.63,236.85 386.08,236.85 387.35,238.12 387.35,239.39 387.99,239.39 388.62,240.03 391.16,240.03 391.8,239.39 398.14,239.39 400.05,237.49 400.05,227.33 v401.32,227.33 | v423.55,226.69 424.18,227.33 429.26,227.33 433.07,223.52 441.96,223.52 442.6,224.16 v443.23,224.16
  Route3 0.254: v360.05,231.78 365.12,236.85 365.12,242.57 v367.03,244.47 | v443.23,224.16 444.5,222.88 444.5,218.44 446.4,216.53 446.4,201.93 447.68,200.66 447.68,193.67 448.94,192.41 447.68,191.13 447.68,189.23 449.58,187.32 449.58,186.06 454.02,181.61 454.02,175.26 455.3,173.99 455.3,173.35 454.02,172.09 454.02,167.64 v452.75,166.37
  Bottom 0.254: v43.18,113.66 42.55,113.03 36.2,113.03 33.02,109.85 26.67,109.85 22.86,106.04 18.41,106.04 17.78,105.41 E39.M2 | v137.79,180.97 142.24,185.42 149.22,185.42 v151.13,187.32 | v401.32,227.33 402.59,227.33 404.5,225.42 405.76,225.42 407.67,227.33 416.56,227.33 417.19,226.69 v423.55,226.69 | v452.75,166.37 445.13,166.37 443.23,168.28 441.32,166.37 441.32,162.56 445.77,162.56 D05.R2
-BAC05  (via drill 0.61)
  Top 0.254: v253.37,5.71 252.73,6.35 v252.73,12.7 | v417.19,25.4 419.1,27.3 419.1,33.66 422.27,36.83 422.27,69.22 419.1,72.39 v419.1,86.36
  Route2 0.254: v253.37,5.71 252.09,4.44 234.31,4.44 232.41,6.35 191.77,6.35 189.87,4.44 175.9,4.44 173.99,6.35 112.39,6.35 104.78,13.97 99.69,13.97 20.32,93.34 17.78,93.34 17.78,97.79 E39.P2 | v335.28,24.77 336.55,23.49 340.36,23.49 341,24.13 349.88,24.13 350.52,23.49 353.06,23.49 353.69,24.13 360.05,24.13 360.68,23.49 365.76,23.49 366.39,24.13 375.29,24.13 375.92,23.49 378.46,23.49 379.1,24.13 386.71,24.13 387.35,23.49 391.16,23.49 394.97,27.3 401.95,27.3 405.76,23.49 415.29,23.49 v417.19,25.4 | v419.1,86.36 420.37,87.63 421.64,87.63 444.5,110.49 444.5,142.24 443.23,142.24 440.06,145.41 440.06,147.32 445.77,153.03 445.77,154.94 D05.T2
  Route3 0.254: v252.73,12.7 254,11.43 259.71,11.43 262.25,8.89 295.27,8.89 295.27,18.41 300.99,24.13 306.07,24.13 v306.07,23.49
  Bottom 0.254: v306.07,23.49 306.7,24.13 309.25,24.13 312.42,27.3 314.96,27.3 315.6,26.67 321.94,26.67 325.12,23.49 327.66,23.49 328.3,24.13 332.74,24.13 333.38,24.77 v335.28,24.77
-BAC06  (via drill 0.61)
  Top 0.254: v361.95,229.23 v361.95,207.01 | v412.75,205.74 417.19,210.19 v417.19,213.36
  Route2 0.254: v67.94,187.96 90.81,210.82 v90.81,217.17 | v417.19,213.36 419.1,215.26 447.04,215.26 448.94,217.17 453.39,217.17 463.55,227.33 463.55,240.03 460.38,240.03 454.02,246.38 454.02,251.46 448.94,256.54 446.4,256.54 C05.F2
  Route3 0.254: v15.88,135.25 15.88,93.98 17.14,92.71 E39.S2 | v61.59,143.51 66.67,148.59 66.67,184.78 67.94,186.06 v67.94,187.96
  Bottom 0.254: v15.88,135.25 15.88,143.51 v61.59,143.51 | v90.81,217.17 103.5,229.87 110.49,229.87 111.76,231.14 114.3,231.14 115.57,229.87 124.46,229.87 125.09,230.5 133.99,230.5 134.62,229.87 137.16,229.87 137.79,230.5 146.69,230.5 147.32,229.87 149.86,229.87 150.5,230.5 159.38,230.5 160.02,229.87 162.56,229.87 163.19,230.5 172.09,230.5 172.72,229.87 175.26,229.87 175.9,230.5 184.78,230.5 185.42,229.87 187.96,229.87 188.59,230.5 197.49,230.5 198.12,229.87 200.66,229.87 201.29,230.5 210.19,230.5 214,226.69 214.63,226.69 217.81,229.87 226.06,229.87 226.69,230.5 233.04,230.5 233.68,229.87 238.76,229.87 239.4,230.5 248.28,230.5 248.92,229.87 251.46,229.87 252.09,230.5 260.99,230.5 261.62,229.87 264.16,229.87 264.8,230.5 273.69,230.5 274.32,229.87 276.86,229.87 277.5,230.5 286.38,230.5 287.02,229.87 289.56,229.87 290.19,230.5 296.55,230.5 297.18,229.87 302.26,229.87 302.89,230.5 311.79,230.5 312.42,229.87 314.96,229.87 315.6,230.5 316.87,230.5 317.5,229.87 327.66,229.87 328.3,230.5 337.19,230.5 337.82,229.87 340.36,229.87 341,230.5 349.88,230.5 350.52,229.87 353.06,229.87 353.69,230.5 360.68,230.5 v361.95,229.23 | v361.95,207.01 362.58,206.38 379.73,206.38 381,207.64 382.9,205.74 v412.75,205.74
-BAC07  (via drill 0.61)
  Top 0.254: v160.02,327.03 165.1,332.11 165.1,337.19 v166.37,338.46
  Route2 0.254: v125.73,323.85 127.64,325.75 137.16,325.75 137.79,325.12 146.69,325.12 150.5,328.93 158.12,328.93 v160.02,327.03 | v166.37,338.46 170.18,342.27 219.07,342.27 220.34,341 223.52,341 226.69,337.82 235.59,337.82 239.4,341.63 249.56,341.63 250.82,342.9 297.18,342.9 298.45,341.63 299.08,342.27 304.17,342.27 304.8,342.9 313.69,342.9 314.96,344.17 335.28,344.17 336.55,345.44 358.14,345.44 359.41,344.17 393.06,344.17 393.7,344.81 402.59,344.81 405.76,341.63 417.83,341.63 438.15,321.31 438.15,271.78 440.06,271.78 v445.77,266.06
  Route3 0.254: v55.24,95.25 57.15,97.16 57.15,104.14 66.67,113.66 66.67,147.32 v67.94,148.59 | v105.41,180.97 107.95,183.51 107.95,201.29 111.12,204.47 111.12,222.88 115.57,227.33 115.57,229.87 114.3,231.14 114.3,259.72 120.65,266.06 120.65,318.77 v125.73,323.85 | v445.77,266.06 445.13,265.43 445.13,264.8 444.5,264.16 444.5,252.73 445.77,251.46 C05.J2
  Bottom 0.254: v55.24,95.25 53.98,93.98 48.9,93.98 45.09,90.17 36.2,90.17 35.56,90.8 29.21,90.8 27.94,92.07 26.67,92.07 24.77,90.17 23.5,90.17 22.86,90.8 15.88,90.8 14.61,89.53 E39.T2 | v67.94,148.59 70.48,151.13 70.48,153.67 73.66,153.67 99.69,179.7 104.14,179.7 v105.41,180.97
-BAC08  (via drill 0.61)
  Top 0.254: v40.01,195.58 41.27,196.85 41.27,214 v40.01,215.26
  Route2 0.254: v41.27,154.31 44.45,157.48 44.45,195.58 v40.01,195.58 | v160.66,217.17 163.19,214.63 219.71,214.63 220.34,214 241.94,214 249.56,206.38 271.78,206.38 276.86,211.45 335.92,211.45 339.09,214.63 388.62,214.63 390.52,212.72 412.12,212.72 415.29,215.9 441.96,215.9 444.5,218.44 444.5,219.71 v445.77,220.98
  Route3 0.254: v36.2,88.9 44.45,97.16 44.45,147.32 41.27,150.5 v41.27,154.31 | v445.77,220.98 445.13,221.61 445.13,224.16 441.32,227.97 441.32,235.59 443.87,238.12 443.87,240.03 445.77,241.94 445.77,243.84 C05.L2
  Bottom 0.254: v36.2,88.9 34.29,86.99 33.02,86.99 29.84,90.17 26.04,90.17 22.86,86.99 14.61,86.99 14.61,83.18 E39.V2 | v40.01,215.26 78.74,215.26 79.38,215.9 80.64,214.63 132.72,214.63 133.99,215.9 143.51,215.9 144.78,217.17 v160.66,217.17
-BAC09  (via drill 0.61)
  Top 0.254: v414.02,282.58 v414.02,273.05
  Route2 0.254: v84.45,376.56 83.82,376.56 83.19,375.92 74.3,375.92 73.66,376.56 62.87,376.56 18.41,332.11 15.88,332.11 14.61,330.84 B39.D2 | v332.11,365.12 333.38,363.86 340.36,363.86 346.71,357.5 353.06,357.5 358.77,351.79 395.61,351.79 396.88,350.52 v398.14,350.52 | v408.31,288.29 v414.02,282.58 | v414.02,273.05 422.91,264.16 422.91,261.62 426.72,261.62 445.77,242.57 445.77,238.76 C05.N2
  Route3 0.254: v84.45,376.56 85.72,377.83 85.72,378.46 124.46,417.2 147.96,417.2 153.03,412.12 v156.84,412.12 | v299.72,410.85 307.98,402.59 307.98,395.61 311.79,391.8 314.96,391.8 315.6,392.43 323.85,392.43 323.85,384.81 330.2,378.46 330.2,367.03 v332.11,365.12 | v398.14,350.52 397.51,349.89 397.51,342.9 400.05,340.36 400.05,327.66 403.23,324.49 403.23,318.77 405.76,316.23 409.57,316.23 409.57,313.69 410.21,313.06 412.12,313.06 412.12,311.15 406.4,305.44 406.4,299.72 405.13,298.45 405.13,297.18 406.4,295.91 406.4,290.2 v408.31,288.29
  Bottom 0.254: v156.84,412.12 157.48,412.75 188.59,412.75 189.87,411.48 196.85,411.48 197.49,412.12 198.75,412.12 200.03,413.39 248.92,413.39 250.19,412.12 266.7,412.12 267.33,411.48 284.48,411.48 285.75,410.21 288.93,410.21 290.19,411.48 292.74,411.48 293.37,410.85 v299.72,410.85
-BAC10  (via drill 0.61)
  Top 0.254: v24.13,316.23 17.14,323.22 17.14,326.39 B39.E2 | v185.42,295.28 187.32,293.37 v187.32,286.39 | v360.05,281.31 365.12,276.23 365.12,271.78 367.67,269.24 367.67,267.97 368.3,267.34 v368.3,241.94
  Route2 0.254: v24.13,316.23 29.21,311.15 29.21,309.88 31.75,309.88 32.38,309.25 32.38,306.71 35.56,306.71 36.2,306.07 41.27,306.07 60.33,287.02 67.94,287.02 72.39,282.58 109.22,282.58 114.3,287.66 124.46,287.66 125.09,287.02 133.99,287.02 140.97,294 149.86,294 150.5,293.37 159.38,293.37 160.02,294 162.56,294 163.19,293.37 172.09,293.37 175.9,297.18 183.51,297.18 v185.42,295.28 | v187.32,286.39 189.87,283.85 250.19,283.85 250.82,284.48 252.09,284.48 255.91,280.67 311.79,280.67 314.96,277.5 350.52,277.5 352.43,279.4 358.14,279.4 v360.05,281.31 | v368.3,241.94 370.2,240.03 377.19,240.03 381,236.22 391.16,236.22 391.8,236.85 393.7,236.85 v394.97,235.59
  Bottom 0.254: v394.97,235.59 395.61,236.22 403.86,236.22 404.5,236.85 413.38,236.85 414.02,236.22 415.93,236.22 417.83,238.12 418.46,238.12 419.74,236.85 426.08,236.85 426.72,236.22 429.26,236.22 429.89,236.85 432.44,236.85 435.61,233.68 440.69,233.68 441.96,232.41 445.77,232.41 C05.R2
-BAC11  (via drill 0.61)
  Top 0.254: v433.7,327.66 431.8,329.56 431.8,372.75 v426.72,377.83 | v263.52,410.21 254.63,419.1 193.68,419.1 v193.68,415.29
  Route2 0.254: v433.7,327.66 439.42,321.95 441.32,321.95 441.32,300.99 445.13,297.18 447.68,297.18 447.68,266.7 446.4,265.43 446.4,264.16 C05.D2 | v426.72,377.83 393.06,411.48 340.36,411.48 327.02,398.15 316.87,398.15 316.23,398.78 314.96,398.78 309.88,393.7 308.61,393.7 307.34,394.97 300.99,394.97 300.36,395.61 297.81,395.61 v297.18,394.97 | v36.2,335.92 21.59,321.31 17.78,321.31 B39.H2
  Route3 0.254: v297.18,394.97 288.29,394.97 284.48,398.78 275.59,398.78 271.78,394.97 262.89,394.97 262.89,396.88 262.25,397.51 262.25,398.15 263.52,399.42 v263.52,410.21 | v193.68,415.29 162.56,415.29 162.56,416.56 157.48,421.64 69.85,421.64 69.85,401.96 38.1,370.21 38.1,337.82 v36.2,335.92
-BM  (via drill 0.61)
  Top 0.254: v55.88,75.56 53.98,77.47 53.98,86.99 52.7,88.27 E36.T2 | v198.75,76.83 200.03,78.1 200.03,93.98 | 200.03,93.98 v200.03,107.95 | 200.03,93.98 v201.93,93.98
  Bottom 0.254: v55.88,75.56 85.72,75.56 87,74.29 110.49,74.29 111.12,74.93 113.03,73.02 144.78,73.02 145.41,73.66 189.87,73.66 193.04,76.83 v198.75,76.83 | v200.03,107.95 204.47,107.95 E24.L2 | v201.93,93.98 202.56,93.34 211.46,93.34 212.09,93.98 219.07,93.98 220.34,92.71 E23.S2
-BMB00  (via drill 0.61)
  Route3 0.254: v7.62,136.53 8.89,137.79 8.89,147.95 9.53,148.59 9.53,198.75 10.79,200.03 v10.79,201.29 | v52.7,216.53 53.98,217.81 53.98,258.44 52.7,259.72 52.7,262.89 C36.D2
  Bottom 0.254: v7.62,136.53 3.17,132.08 1.91,132.08 1.91,127.63 E40.D2 | v10.79,201.29 12.06,201.29 27.3,216.53 v52.7,216.53
-BMB01  (via drill 0.61)
  Top 0.254: v13.97,130.81 17.14,133.99 v17.14,134.62
  Route2 0.254: v46.35,212.72 46.35,217.17 50.8,221.61 50.8,256.54 52.07,256.54 C36.F2
  Route3 0.254: v46.35,137.16 47.62,138.43 47.62,211.45 v46.35,212.72
  Bottom 0.254: v13.97,130.81 8.26,125.09 5.71,125.09 5.08,124.46 E40.E2 | v17.14,134.62 17.78,135.25 20.32,135.25 23.5,138.43 45.09,138.43 v46.35,137.16
-BMB02  (via drill 0.61)
  Top 0.254: v3.17,196.85 3.17,235.59 v4.45,236.85 | v52.07,248.28 52.07,250.19 C36.J2
  Route3 0.254: v6.35,184.15 6.35,180.34 7.62,179.07 7.62,176.53 6.35,175.26 6.35,123.19 5.71,122.55 5.71,118.74 5.08,118.11 E40.H2
  Bottom 0.254: v6.35,184.15 6.35,195.58 3.81,195.58 3.17,196.22 v3.17,196.85 | v4.45,236.85 13.97,246.38 22.86,246.38 26.67,242.57 35.56,242.57 39.37,246.38 48.26,246.38 48.9,245.75 49.53,245.75 v52.07,248.28
-BMB03  (via drill 0.61)
  Route3 0.254: v17.14,114.3 19.05,116.2 19.05,138.43 20.95,140.34 20.95,147.32 22.23,148.59 22.23,179.07 23.5,180.34 23.5,180.97 v22.23,182.25 | v29.21,193.67 28.57,194.31 28.57,208.28 29.84,209.55 29.84,220.34 28.57,221.61 28.57,282.58 31.75,285.75 31.75,313.06 v36.2,317.5
  Bottom 0.254: v17.14,114.3 8.89,106.04 5.71,106.04 5.08,105.41 E40.M2 | v22.23,182.25 22.23,188.59 24.13,188.59 v29.21,193.67 | v36.2,317.5 39.37,317.5 B37.J2
-BMB04  (via drill 0.61)
  Top 0.254: v60.33,254 60.33,271.78 56.52,275.59 56.52,285.75 v55.88,286.39
  Route2 0.254: v55.88,286.39 40.01,302.26 40.01,304.17 B37.N2
  Route3 0.254: v52.7,97.79 52.7,99.06 50.8,100.96 50.8,108.58 57.15,114.93 57.15,120.02 55.88,121.28 55.88,121.92 57.15,123.19 57.15,144.78 60.33,147.95 60.33,176.53 59.05,177.8 59.05,179.07 60.33,180.34 v60.33,254
  Bottom 0.254: v52.7,97.79 49.53,94.61 48.9,94.61 43.81,99.69 40.64,99.69 37.47,96.52 36.2,96.52 32.38,100.33 23.5,100.33 17.14,93.98 10.79,93.98 10.16,93.34 5.71,93.34 5.08,92.71 E40.S2
-BMB05  (via drill 0.61)
  Top 0.254: v23.5,95.25 25.4,97.16 25.4,118.74 v26.04,119.38
  Route3 0.254: v26.04,119.38 29.21,119.38 29.84,118.74 31.75,118.74 31.75,163.19 34.92,166.37 34.92,173.99 38.1,177.16 38.1,189.86 39.37,191.13 39.37,191.77 38.1,193.04 38.1,223.52 35.56,226.06 35.56,227.33 34.92,227.97 34.92,280.04 36.2,281.31 36.2,287.02 34.92,288.29 v34.92,291.47
  Bottom 0.254: v23.5,95.25 21.59,93.34 16.51,93.34 10.16,86.99 1.91,86.99 1.91,83.18 E40.V2 | v34.92,291.47 39.37,291.47 B37.T2
-BMB06  (via drill 0.61)
  Top 0.254: v288.93,385.45 293.37,389.89 293.37,393.06 A17.F2
  Route2 0.254: v1.91,201.93 3.17,201.93 3.17,199.39 2.54,198.75 1.91,198.75 1.91,196.85 3.17,195.58 4.45,195.58 4.45,191.13 D40.E2 | v168.28,377.19 168.91,376.56 175.26,376.56 175.9,375.92 184.78,375.92 191.77,382.91 200.66,382.91 201.29,382.27 210.19,382.27 214,386.08 222.88,386.08 223.52,385.45 226.06,385.45 229.87,389.25 236.85,389.25 240.66,385.45 251.46,385.45 255.27,389.25 264.16,389.25 267.97,385.45 276.86,385.45 277.5,386.08 286.38,386.08 287.02,385.45 v288.93,385.45
  Route3 0.254: v15.24,241.94 17.14,243.84 17.14,245.75 15.88,247.01 v15.88,277.5 | v84.45,288.93 88.9,293.37 88.9,305.44 91.44,307.98 88.9,310.52 88.9,345.44 111.12,367.67 111.12,372.75 v113.03,374.65
  Bottom 0.254: v1.91,201.93 1.91,217.81 2.54,217.81 12.7,227.97 12.7,239.39 v15.24,241.94 | v15.88,277.5 20.95,282.58 20.95,283.85 21.59,283.85 22.23,284.48 27.94,284.48 28.57,285.12 31.75,285.12 33.02,283.85 48.26,283.85 52.07,287.66 60.96,287.66 61.59,287.02 70.48,287.02 71.12,287.66 73.66,287.66 74.3,287.02 79.38,287.02 80.64,285.75 81.28,285.75 v84.45,288.93 | v113.03,374.65 114.94,376.56 124.46,376.56 125.09,375.92 133.99,375.92 134.62,376.56 137.16,376.56 137.79,375.92 146.69,375.92 150.5,379.73 151.76,379.73 154.94,376.56 162.56,376.56 163.19,375.92 167,375.92 v168.28,377.19
-BMB07  (via drill 0.61)
  Route2 0.254: v26.67,172.72 25.4,172.72 25.4,180.34 20.32,185.42 16.51,185.42 10.16,179.07 5.71,179.07 5.08,178.44 D40.K2 | v68.58,173.35 75.56,166.37 81.92,166.37 85.09,163.19 95.89,163.19 105.41,172.72 111.76,172.72 118.11,179.07 124.46,179.07 125.09,179.7 131.44,179.7 140.97,189.23 147.96,189.23 151.13,186.06 154.94,186.06 157.48,188.59 159.38,188.59 163.19,192.41 v163.83,192.41 | v172.72,190.5 177.8,185.42 185.42,185.42 204.47,166.37 213.36,166.37 219.71,172.72 226.06,172.72 232.41,179.07 238.76,179.07 239.4,179.7 243.84,179.7 v252.73,188.59 | v274.95,185.42 281.31,191.77 289.56,191.77 293.37,195.58 302.26,195.58 302.89,194.94 311.79,194.94 312.42,195.58 314.96,195.58 315.6,194.94 324.49,194.94 331.47,201.93 335.92,201.93 v337.82,203.84 | v396.88,217.17 408.31,217.17 421,229.87 429.26,229.87 429.89,230.5 437.51,230.5 441.96,226.06 445.77,226.06 C05.T2
  Route3 0.254: v337.82,203.84 342.26,208.28 342.26,218.44 342.9,219.07 342.9,219.71 v344.81,221.61
  Bottom 0.254: v26.67,172.72 35.56,172.72 39.37,176.53 48.26,176.53 48.9,175.89 57.78,175.89 58.42,176.53 60.96,176.53 64.14,173.35 v68.58,173.35 | v163.83,192.41 164.47,191.77 171.45,191.77 v172.72,190.5 | v252.73,188.59 253.37,189.23 260.35,189.23 260.99,189.86 263.52,189.86 264.8,188.59 271.14,188.59 274.32,185.42 v274.95,185.42 | v344.81,221.61 345.44,220.98 353.06,220.98 356.87,217.17 364.49,217.17 365.12,217.81 365.76,217.81 367.03,216.53 396.24,216.53 v396.88,217.17
-BMB08  (via drill 0.61)
  Top 0.254: v128.27,273.69 132.08,277.5 v132.08,285.12 | v277.5,278.13 279.4,276.23 279.4,255.27 v280.67,254
  Route2 0.254: v90.81,240.66 118.11,267.97 122.56,267.97 v128.27,273.69 | v132.08,285.12 134.62,282.58 199.39,282.58 200.03,283.21 249.56,283.21 253.37,279.4 276.23,279.4 v277.5,278.13 | v280.67,254 281.94,255.27 289.56,255.27 290.19,255.91 290.83,255.91 291.46,255.27 298.45,255.27 304.8,248.92 314.96,248.92 318.77,252.73 327.02,252.73 333.38,246.38 340.36,246.38 341.63,245.11 344.17,245.11 C13.L2
  Route3 0.254: v87.63,182.25 88.9,183.51 88.9,238.76 v90.81,240.66
  Bottom 0.254: v87.63,182.25 84.45,179.07 83.82,179.07 83.19,179.7 74.3,179.7 73.66,179.07 71.12,179.07 70.48,179.7 61.59,179.7 60.96,179.07 58.42,179.07 57.78,179.7 48.9,179.7 48.26,179.07 45.72,179.07 45.09,179.7 36.2,179.7 34.29,177.8 33.66,177.8 32.38,179.07 29.21,179.07 19.68,169.54 10.79,169.54 10.16,170.18 5.08,170.18 5.08,165.73 D40.P2
-BMB09  (via drill 0.61)
  Route3 0.254: v36.83,167.64 41.27,172.09 41.27,185.42 43.81,187.96 42.55,189.23 41.27,189.23 v41.27,241.94
  Bottom 0.254: v36.83,167.64 32.38,163.19 23.5,163.19 22.86,163.83 13.97,163.83 10.16,160.02 5.71,160.02 5.08,159.38 D40.S2 | v41.27,241.94 41.91,242.57 48.26,242.57 49.53,243.84 52.07,243.84 C36.L2
-BMB10  (via drill 0.61)
  Top 0.254: v10.79,168.28 12.7,170.18 12.7,188.59 17.78,193.67 v17.78,194.94 | v50.8,209.55 50.8,236.22 52.07,237.49 C36.N2
  Route2 0.254: v17.78,194.94 32.38,209.55 v36.83,209.55
  Bottom 0.254: v10.79,168.28 3.17,160.66 1.91,160.66 1.91,156.21 D40.T2 | v50.8,209.55 v36.83,209.55
-BMB11  (via drill 0.61)
  Top 0.254: v64.77,144.78 66.67,146.69 66.67,214.63 63.5,217.81 63.5,223.52 v61.59,225.42
  Route3 0.254: v1.91,144.78 1.91,148.59 D40.V2
  Bottom 0.254: v64.77,144.78 v1.91,144.78 | v61.59,225.42 59.69,227.33 54.61,227.33 52.7,229.23 52.7,231.14 C36.R2
-BT00  (via drill 0.61)
  Top 0.254: v184.15,390.53 184.15,386.08 182.88,384.81 A26.K2
  Bottom 0.254: v184.15,390.53 185.42,391.8 187.96,391.8 191.77,395.61 200.66,395.61 201.29,394.97 206.38,394.97 207.65,396.24 A24.E2
-BT00(B)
